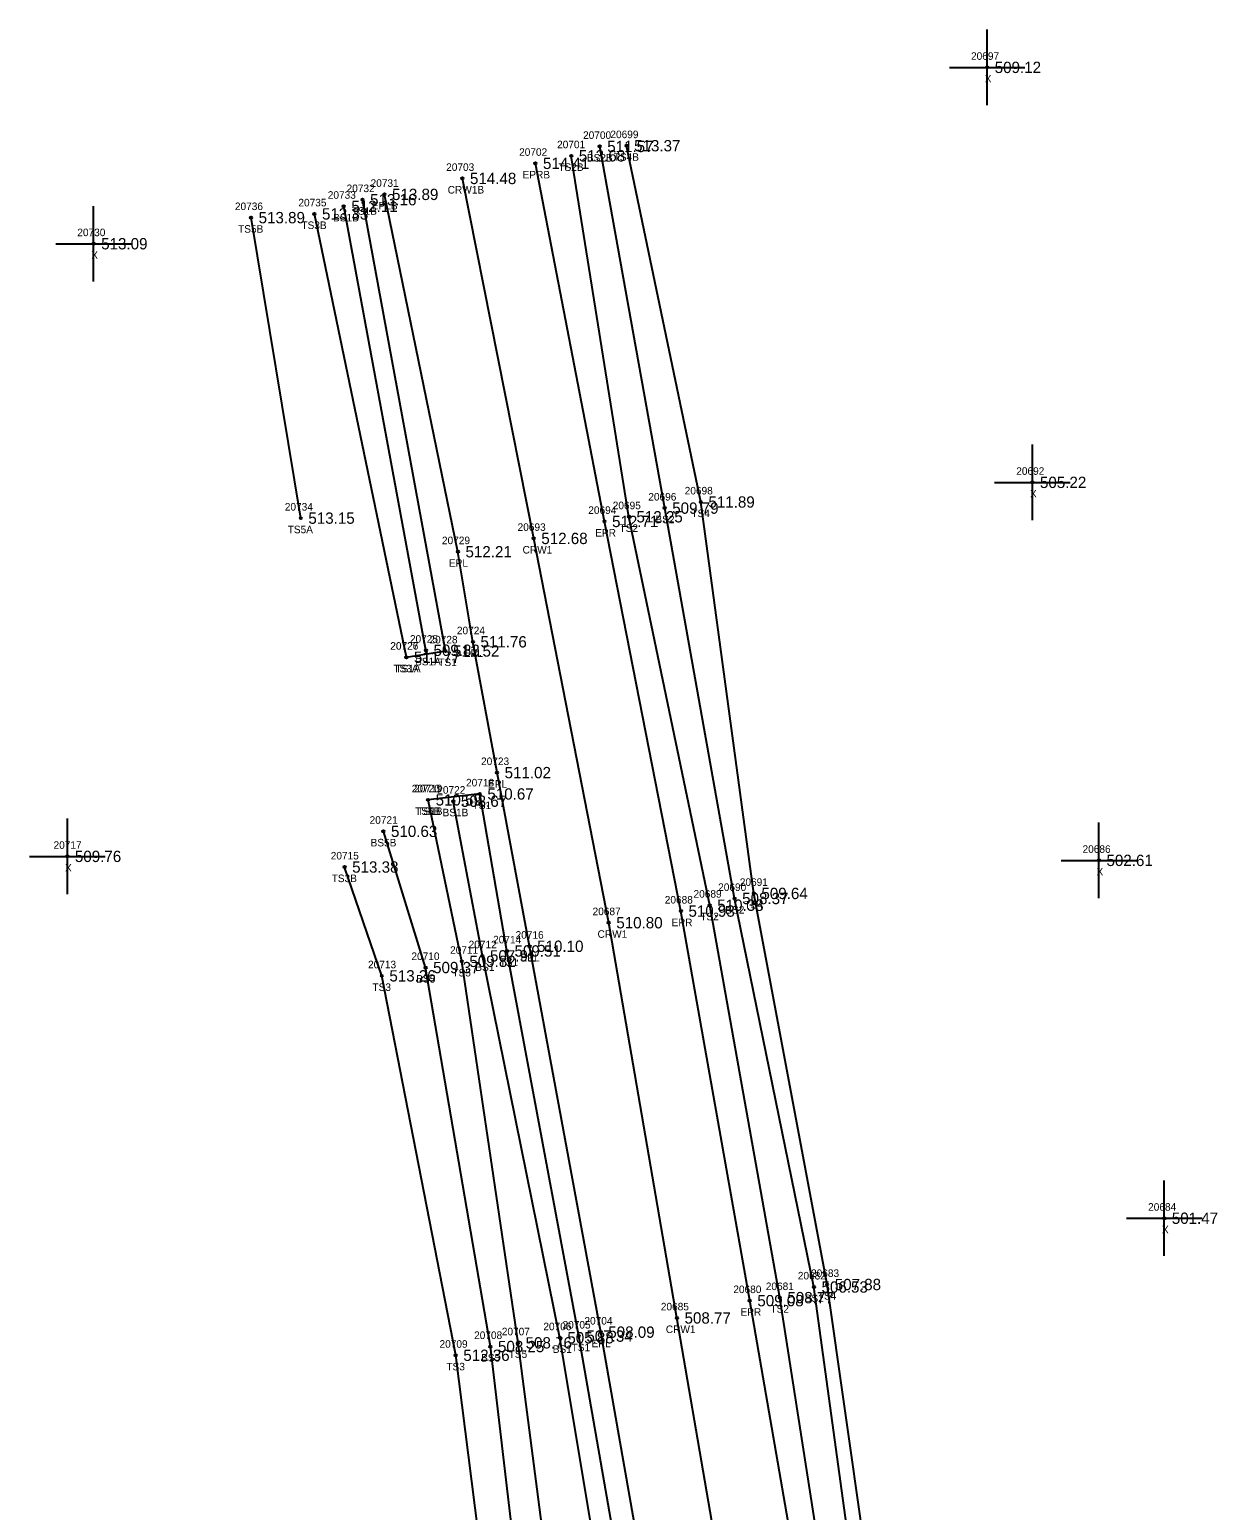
# Model space of a CAD drawing. Extents: x 1649406 to 1650436, y 896752 to 898178.
# Drawn here: x 1649837.8 to 1649995.1, y 897981.4 to 898177.7 of the extents above; entities that cross this region are included whole.
import ezdxf

# ---------------------------------------------------------------- set-up
doc = ezdxf.new("R2010")
doc.units = 0
for name, color, linetype in [('RD_DTM_BkLn1', 7, 'Continuous'), ('RD_DTM_BkLn2', 7, 'Continuous'), ('RD_DTM_BkLn_txCode', 7, 'Continuous'), ('RD_EX_Misc', 7, 'Continuous'), ('RD_EX_Misc_txCode', 7, 'Continuous'), ('RD_EX_Road', 7, 'Continuous'), ('RD_EX_Road_txCode', 7, 'Continuous'), ('RD_EX_TX_Misc_ELEV', 7, 'Continuous'), ('RD_EX_TX_Road_ELEV', 7, 'Continuous'), ('RD_HC_Survey_ELEV', 7, 'Continuous'), ('RD_HC_Survey_txCode', 7, 'Continuous'), ('RD_SMD_Locator', 7, 'Continuous')]:
    doc.layers.add(name, color=color, linetype=linetype)

msp = doc.modelspace()

# ---------------------------------------------------------------- linework, layer by layer
at = {"layer": 'RD_DTM_BkLn1'}
msp.add_lwpolyline([(1649894.9, 897462.66), (1649908.82, 897514.7), (1649920.62, 897564.87), (1649930.21, 897614.13), (1649937.18, 897663.59), (1649942.29, 897713.83), (1649944.94, 897762.9), (1649945.25, 897813.29), (1649942.44, 897857.84), (1649938.23, 897907.76), (1649931.88, 897958.19), (1649923.51, 898006.94), (1649914.47, 898059.31), (1649904.54, 898110.23), (1649895.09, 898157.93)], dxfattribs=at)
at = {"layer": 'RD_DTM_BkLn2'}
for p, q in [((1649873.69, 898112.92), (1649867.1, 898152.74)), ((1649887.67, 898094.49), (1649875.49, 898153.23)), ((1649890.26, 898095.41), (1649879.38, 898154.24))]:
    msp.add_line(p, q, dxfattribs=at)
for points in [[(1649958.96, 897790.24), (1649962.39, 897790.68), (1649967.64, 897797.03), (1649970.07, 897811.8), (1649970.48, 897838.78), (1649967.21, 897860.09), (1649958.68, 897911.21), (1649950.58, 897960.83), (1649943.4, 898011.37), (1649933.69, 898063.19), (1649926.67, 898115.06), (1649916.83, 898162.27)], [(1649958.96, 897790.24), (1649958.53, 897812.59), (1649955.38, 897860.08), (1649951.36, 897910.68), (1649944.83, 897960.41), (1649937.13, 898009.63), (1649927.84, 898061.63), (1649917.14, 898113.1), (1649909.51, 898160.93)], [(1649960.73, 897791.43), (1649960.66, 897812.69), (1649958.13, 897861.33), (1649953.81, 897911.34), (1649948.42, 897961.49), (1649941.65, 898011.04), (1649931.14, 898062.52), (1649921.88, 898114.25), (1649913.27, 898162.17)], [(1649887.67, 898094.49), (1649892.85, 898095.32), (1649881.86, 898155.12)], [(1649920.87, 897644.21), (1649923.9, 897665.21), (1649928.63, 897702.34), (1649930.33, 897715.28), (1649933.79, 897763.23), (1649933.69, 897813.91), (1649929.49, 897857.74), (1649925.75, 897907.07), (1649919.24, 897954.42), (1649910.51, 898004.53), (1649900.99, 898055.57), (1649897.4, 898076.37), (1649890.54, 898075.59)], [(1649920.09, 897873.37), (1649916.99, 897906.82), (1649909.17, 897951.9), (1649902.46, 898003.64), (1649895.01, 898054.19), (1649890.54, 898075.59)], [(1649902.31, 897569.09), (1649911.24, 897617.29), (1649920.65, 897666.08), (1649926.58, 897702.16), (1649928.32, 897715.46), (1649931.24, 897763.41), (1649931.43, 897814), (1649927.03, 897856.89), (1649923.37, 897907.61), (1649916.38, 897954.04), (1649907.99, 898004.31), (1649897.74, 898054.92), (1649893.88, 898075.41)], [(1649920.09, 897873.37), (1649913.59, 897907.24), (1649904.9, 897951.32), (1649898.8, 898003.15), (1649890.21, 898053.37), (1649884.63, 898071.42)], [(1649868.11, 897593.32), (1649891.92, 897625.99), (1649904.5, 897665.19), (1649913.68, 897716.44), (1649912.45, 897760.99), (1649915.73, 897816.74), (1649911.68, 897855.77), (1649908.62, 897888.32), (1649894.21, 898001.99), (1649884.42, 898052.27), (1649879.49, 898066.69)]]:
    msp.add_lwpolyline(points, dxfattribs=at)
at = {"layer": 'RD_EX_Misc'}
for p, q in [((1649964.59, 898167.65), (1649964.59, 898177.65)), ((1649959.59, 898172.65), (1649969.59, 898172.65)), ((1649846.25, 898144.28), (1649846.25, 898154.28)), ((1649841.25, 898149.28), (1649851.25, 898149.28)), ((1649970.58, 898112.66), (1649970.58, 898122.66)), ((1649965.58, 898117.66), (1649975.58, 898117.66)), ((1649842.77, 898063.1), (1649842.77, 898073.1)), ((1649979.39, 898062.57), (1649979.39, 898072.57)), ((1649837.77, 898068.1), (1649847.77, 898068.1)), ((1649974.39, 898067.57), (1649984.39, 898067.57)), ((1649988.04, 898015.15), (1649988.04, 898025.15)), ((1649983.04, 898020.15), (1649993.04, 898020.15))]:
    msp.add_line(p, q, dxfattribs=at)
at = {"layer": 'RD_EX_Road'}
for points in [[(1649905.13, 897459.2), (1649918.81, 897511.88), (1649930.39, 897563.05), (1649939.7, 897612.37), (1649946.83, 897662.25), (1649952.14, 897712.87), (1649954.77, 897762.63), (1649955.64, 897791.88), (1649955.33, 897812.31), (1649952.46, 897859.75), (1649947.95, 897909.71), (1649941.78, 897959.51), (1649933.15, 898009.23), (1649924.03, 898060.85), (1649913.91, 898112.48), (1649904.76, 898159.93)], [(1649885.84, 897465.29), (1649899.42, 897516.76), (1649910.69, 897567.43), (1649919.68, 897616.11), (1649926.54, 897664.67), (1649931.97, 897714.33), (1649935.04, 897763.32), (1649935.22, 897813.54), (1649932.16, 897857.76), (1649927.73, 897907.79), (1649922.24, 897954.81), (1649913.41, 898005.06), (1649903.99, 898056.19), (1649899.68, 898079.2), (1649896.48, 898096.53), (1649894.5, 898108.47), (1649884.77, 898155.82)]]:
    msp.add_lwpolyline(points, dxfattribs=at)
at = {"layer": 'RD_SMD_Locator'}
for centre in [(1649964.59, 898172.65), (1649913.27, 898162.17), (1649916.83, 898162.27), (1649909.51, 898160.93), (1649904.76, 898159.93), (1649895.09, 898157.93), (1649879.38, 898154.24), (1649881.86, 898155.12), (1649884.77, 898155.82), (1649867.1, 898152.74), (1649875.49, 898153.23), (1649846.25, 898149.28), (1649970.58, 898117.66), (1649926.67, 898115.06), (1649917.14, 898113.1), (1649921.88, 898114.25), (1649873.69, 898112.92), (1649913.91, 898112.48), (1649904.54, 898110.23), (1649894.5, 898108.47), (1649890.26, 898095.41), (1649892.85, 898095.32), (1649896.48, 898096.53), (1649887.67, 898094.49), (1649887.67, 898094.49), (1649899.68, 898079.2), (1649897.4, 898076.37), (1649890.54, 898075.59), (1649890.54, 898075.59), (1649893.88, 898075.41), (1649884.63, 898071.42), (1649842.77, 898068.1), (1649879.49, 898066.69), (1649979.39, 898067.57), (1649931.14, 898062.52), (1649933.69, 898063.19), (1649924.03, 898060.85), (1649927.84, 898061.63), (1649914.47, 898059.31), (1649903.99, 898056.19), (1649895.01, 898054.19), (1649897.74, 898054.92), (1649900.99, 898055.57), (1649884.42, 898052.27), (1649890.21, 898053.37), (1649988.04, 898020.15), (1649941.65, 898011.04), (1649943.4, 898011.37), (1649933.15, 898009.23), (1649937.13, 898009.63), (1649913.41, 898005.06), (1649923.51, 898006.94), (1649898.8, 898003.15), (1649902.46, 898003.64), (1649907.99, 898004.31), (1649910.51, 898004.53), (1649894.21, 898001.99)]:
    msp.add_circle(centre, 0.15, dxfattribs=at)

# ---------------------------------------------------------------- texts
at = {"layer": 'RD_DTM_BkLn_txCode'}
for s, p in [('20700', (1649911.07, 898163.17)), ('20699', (1649914.69, 898163.27)), ('20701', (1649907.63, 898161.93)), ('BS2B', (1649911.57, 898160.17)), ('TS4B', (1649915.12, 898160.27)), ('TS2B', (1649907.79, 898158.93)), ('20732', (1649879.75, 898156.12)), ('20736', (1649864.96, 898153.74)), ('20735', (1649873.37, 898154.23)), ('20733', (1649877.26, 898155.24)), ('BS1B', (1649877.96, 898152.24)), ('TS1B', (1649880.43, 898153.12)), ('TS5B', (1649865.38, 898150.74)), ('TS3B', (1649873.77, 898151.23)), ('20698', (1649924.53, 898116.06)), ('20695', (1649915, 898114.1)), ('20696', (1649919.71, 898115.25)), ('20734', (1649871.57, 898113.92)), ('BS2', (1649920.65, 898112.25)), ('TS4', (1649925.42, 898113.06)), ('TS5A', (1649871.95, 898110.92)), ('TS2', (1649915.9, 898111.1)), ('20725', (1649888.14, 898096.41)), ('20726', (1649885.53, 898095.49)), ('20727', (1649885.55, 898095.49)), ('20728', (1649890.73, 898096.32)), ('TS3A', (1649885.94, 898092.49)), ('TS1A', (1649886.22, 898092.49)), ('BS1A', (1649888.82, 898093.41)), ('TS1', (1649891.89, 898093.32)), ('20718', (1649895.57, 898077.37)), ('20720', (1649888.38, 898076.59)), ('20719', (1649888.7, 898076.59)), ('20722', (1649891.76, 898076.41)), ('TS5B', (1649888.82, 898073.59)), ('TS1B', (1649889.11, 898073.59)), ('BS1B', (1649892.46, 898073.41)), ('TS1', (1649896.44, 898074.37)), ('20721', (1649882.8, 898072.42)), ('BS5B', (1649882.93, 898069.42)), ('20715', (1649877.65, 898067.69)), ('TS3B', (1649877.77, 898064.69)), ('20690', (1649928.96, 898063.52)), ('20691', (1649931.83, 898064.19)), ('20689', (1649925.7, 898062.63)), ('TS4', (1649932.45, 898061.19)), ('TS2', (1649926.6, 898059.63)), ('BS2', (1649929.91, 898060.52)), ('20712', (1649895.91, 898055.92)), ('20714', (1649899.16, 898056.57)), ('20713', (1649882.59, 898053.27)), ('20710', (1649888.34, 898054.37)), ('20711', (1649893.46, 898055.19)), ('TS1', (1649900.03, 898053.57)), ('BS5', (1649888.98, 898051.37)), ('TS5', (1649893.76, 898052.19)), ('BS1', (1649896.8, 898052.92)), ('TS3', (1649883.18, 898050.27)), ('20682', (1649939.51, 898012.04)), ('20683', (1649941.26, 898012.37)), ('20681', (1649935.27, 898010.63)), ('BS2', (1649940.42, 898009.04)), ('TS4', (1649942.15, 898009.37)), ('TS2', (1649935.89, 898007.63)), ('20707', (1649900.31, 898004.64)), ('20706', (1649905.81, 898005.31)), ('20705', (1649908.35, 898005.53)), ('20709', (1649892.06, 898002.99)), ('20708', (1649896.64, 898004.15)), ('BS1', (1649907.05, 898002.31)), ('TS1', (1649909.55, 898002.53)), ('BS5', (1649897.57, 898001.15)), ('TS5', (1649901.22, 898001.64)), ('TS3', (1649892.97, 897999.99))]:
    msp.add_text(s, height=1, dxfattribs=at).set_placement(p)
at = {"layer": 'RD_EX_Misc_txCode'}
for s, p in [('20697', (1649962.45, 898173.65)), ('X', (1649964.27, 898170.65)), ('20730', (1649844.09, 898150.28)), ('X', (1649845.93, 898147.28)), ('20692', (1649968.44, 898118.66)), ('X', (1649970.26, 898115.66)), ('20717', (1649840.94, 898069.1)), ('20686', (1649977.22, 898068.57)), ('X', (1649842.46, 898066.1)), ('X', (1649979.07, 898065.57)), ('20684', (1649985.9, 898021.15)), ('X', (1649987.73, 898018.15))]:
    msp.add_text(s, height=1, dxfattribs=at).set_placement(p)
at = {"layer": 'RD_EX_Road_txCode'}
for s, p in [('20702', (1649902.6, 898160.93)), ('EPRB', (1649903.06, 898157.93)), ('20731', (1649882.93, 898156.82)), ('EPLB', (1649883.09, 898153.82)), ('20694', (1649911.76, 898113.48)), ('EPR', (1649912.68, 898110.48)), ('20729', (1649892.38, 898109.47)), ('EPL', (1649893.3, 898106.47)), ('20724', (1649894.36, 898097.53)), ('EPL', (1649895.28, 898094.53)), ('20723', (1649897.56, 898080.2)), ('EPL', (1649898.48, 898077.2)), ('20688', (1649921.89, 898061.85)), ('20716', (1649902.13, 898057.19)), ('EPR', (1649922.8, 898058.85)), ('EPL', (1649902.79, 898054.19)), ('20680', (1649930.97, 898010.23)), ('EPR', (1649931.92, 898007.23)), ('20704', (1649911.25, 898006.06)), ('EPL', (1649912.2, 898003.06))]:
    msp.add_text(s, height=1, dxfattribs=at).set_placement(p)
at = {"layer": 'RD_EX_TX_Misc_ELEV'}
for s, p in [('509.12', (1649965.59, 898171.9)), ('511.57', (1649914.27, 898161.42)), ('513.37', (1649917.83, 898161.52)), ('513.68', (1649910.51, 898160.18)), ('512.11', (1649880.38, 898153.49)), ('513.16', (1649882.86, 898154.37)), ('513.89', (1649868.1, 898151.99)), ('513.33', (1649876.49, 898152.48)), ('513.09', (1649847.25, 898148.53)), ('505.22', (1649971.58, 898116.91)), ('511.89', (1649927.67, 898114.31)), ('513.15', (1649874.69, 898112.17)), ('512.25', (1649918.14, 898112.35)), ('509.79', (1649922.88, 898113.5)), ('509.83', (1649891.26, 898094.66)), ('511.52', (1649893.85, 898094.57)), ('511.77', (1649888.67, 898093.74)), ('511.77', (1649888.67, 898093.74)), ('510.59', (1649891.54, 898074.84)), ('510.59', (1649891.54, 898074.84)), ('508.67', (1649894.88, 898074.66)), ('510.67', (1649898.4, 898075.62)), ('510.63', (1649885.63, 898070.67)), ('509.76', (1649843.77, 898067.35)), ('502.61', (1649980.39, 898066.82)), ('513.38', (1649880.49, 898065.94)), ('510.38', (1649928.84, 898060.88)), ('508.37', (1649932.14, 898061.77)), ('509.64', (1649934.69, 898062.44)), ('509.51', (1649901.99, 898054.82)), ('509.82', (1649896.01, 898053.44)), ('507.91', (1649898.74, 898054.17)), ('513.26', (1649885.42, 898051.52)), ('509.37', (1649891.21, 898052.62)), ('501.47', (1649989.04, 898019.4)), ('506.53', (1649942.65, 898010.29)), ('507.88', (1649944.4, 898010.62)), ('508.77', (1649938.13, 898008.88)), ('507.34', (1649911.51, 898003.78)), ('508.25', (1649899.8, 898002.4)), ('508.76', (1649903.46, 898002.89)), ('505.88', (1649908.99, 898003.56)), ('512.36', (1649895.21, 898001.24))]:
    msp.add_text(s, height=1.5, dxfattribs=at).set_placement(p)
at = {"layer": 'RD_EX_TX_Road_ELEV'}
for s, p in [('514.41', (1649905.76, 898159.18)), ('513.89', (1649885.77, 898155.07)), ('512.71', (1649914.91, 898111.73)), ('512.21', (1649895.5, 898107.72)), ('511.76', (1649897.48, 898095.78)), ('511.02', (1649900.68, 898078.45)), ('510.93', (1649925.03, 898060.1)), ('510.10', (1649904.99, 898055.44)), ('509.08', (1649934.15, 898008.48)), ('508.09', (1649914.41, 898004.31))]:
    msp.add_text(s, height=1.5, dxfattribs=at).set_placement(p)
at = {"layer": 'RD_HC_Survey_ELEV'}
for s, p in [('514.48', (1649896.09, 898157.18)), ('512.68', (1649905.54, 898109.48)), ('510.80', (1649915.47, 898058.56)), ('508.77', (1649924.51, 898006.19))]:
    msp.add_text(s, height=1.5, dxfattribs=at).set_placement(p)
at = {"layer": 'RD_HC_Survey_txCode'}
for s, p in [('20703', (1649892.94, 898158.93)), ('CRW1B', (1649893.14, 898155.93)), ('20693', (1649902.4, 898111.23)), ('CRW1', (1649903.06, 898108.23)), ('20687', (1649912.33, 898060.31)), ('CRW1', (1649912.99, 898057.31)), ('20685', (1649921.37, 898007.94)), ('CRW1', (1649922.03, 898004.94))]:
    msp.add_text(s, height=1, dxfattribs=at).set_placement(p)

doc.saveas('drawing.dxf')
